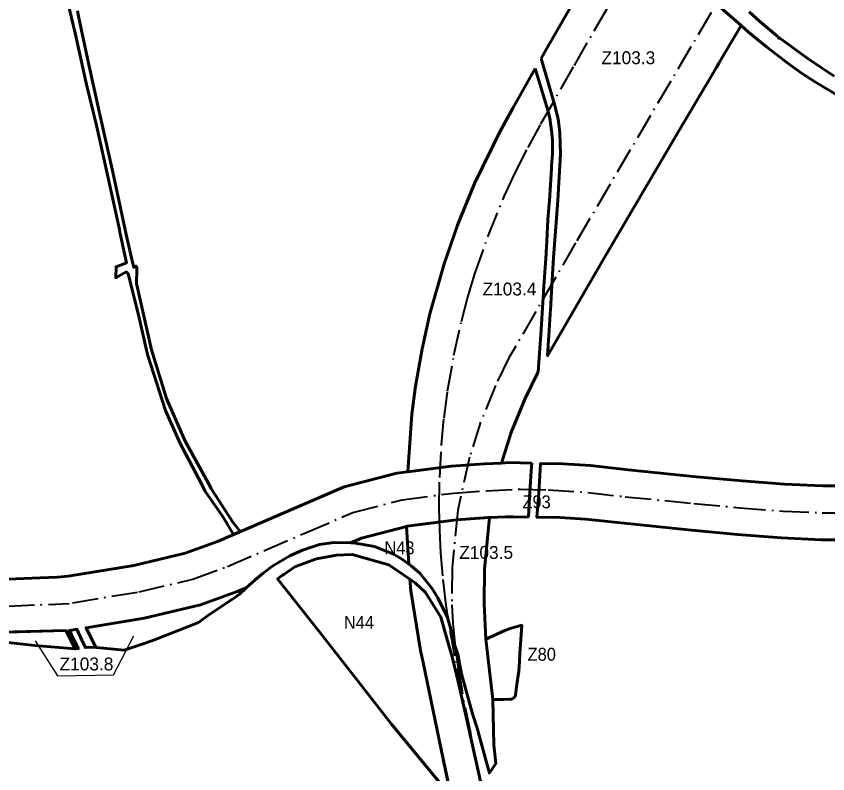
# Model space of a CAD drawing. Extents: x -650277 to -643420, y -1073980 to -1066720.
# Drawn here: x -648765 to -647259, y -1069529 to -1068122 of the extents above; entities that cross this region are included whole.
import ezdxf

# ---------------------------------------------------------------- set-up
doc = ezdxf.new("R2010")
doc.units = 0
doc.header["$LTSCALE"] = 9.6
doc.linetypes.add('DOT_DASHED', pattern=[7.7, 5, -1.2, 0.3, -1.2])
for name, color, linetype, lineweight in [('15', 7, 'Continuous', 60), ('42', 7, 'Continuous', 60), ('60', 7, 'Continuous', 60), ('61', 7, 'Continuous', 60), ('62', 7, 'DOT_DASHED', 40), ('63', 7, 'Continuous', 25), ('9', 7, 'Continuous', 60)]:
    doc.layers.add(name, color=color, linetype=linetype, lineweight=lineweight)

msp = doc.modelspace()

# ---------------------------------------------------------------- linework, layer by layer
at = {"layer": '15'}
for points in [[(-648349.419, -1069079.223), (-648362.06, -1069084.664), (-648381.44, -1069052.48), (-648415.29, -1069003.16), (-648419.78, -1068994.25), (-648427.21, -1068980.13), (-648461.22, -1068915.44), (-648488.09, -1068854.16), (-648521.92, -1068750.34), (-648537.29, -1068681.95), (-648557.4, -1068599.9), (-648559.44, -1068598.37), (-648561.49, -1068596.84), (-648580.66, -1068607.64), (-648579.97, -1068587.39), (-648560.79, -1068580.12), (-648572.95, -1068522.97), (-648573.96, -1068518.34), (-648594.38, -1068425.02), (-648615.87, -1068327.3), (-648634.84, -1068248.76), (-648655.88, -1068153.63), (-648662.71, -1068124.76), (-648677.61, -1068061.74)], [(-648651.89, -1068111.95), (-648649.74, -1068121.95), (-648644.73, -1068145.27), (-648630.99, -1068209.19), (-648610.14, -1068304.32), (-648587.39, -1068405.82), (-648559.91, -1068532.62), (-648549.84, -1068578.65), (-648547.25, -1068588.14), (-648542.93, -1068586.13), (-648541.74, -1068589.27)], [(-648541.74, -1068589.27), (-648541.25, -1068592.3), (-648541.89, -1068618.64), (-648514.35, -1068741.53), (-648486.25, -1068831.83), (-648451.76, -1068910.91), (-648409.15, -1068988.44), (-648402.76, -1069000.2), (-648363.11, -1069061.72), (-648349.419, -1069079.223)]]:
    msp.add_lwpolyline(points, dxfattribs=at)
at = {"layer": '42'}
msp.add_lwpolyline([(-648100.37, -1069107.1), (-648065.16, -1069121.12), (-648048.06, -1069130.81), (-648036.291, -1069139.458), (-648040.705, -1069069.547), (-648124.327, -1069091.181), (-648144.867, -1069099.987), (-648139.27, -1069100.05), (-648100.37, -1069107.1)], close=True, dxfattribs=at)
at = {"layer": '60'}
for points in [[(-647618.773, -1067899.914), (-647553.628, -1067999.427), (-647472.338, -1068093.096), (-647419.713, -1068138.871)], [(-647246.8, -1068233.08), (-647295.47, -1068201.09), (-647347.74, -1068162.54), (-647349.59, -1068163.24), (-647350.6, -1068160.26), (-647353.81, -1068157.67), (-647385.13, -1068131.51), (-647405.026, -1068113.904)], [(-647419.713, -1068138.871), (-647405.71, -1068151.74), (-647372.38, -1068179.01), (-647337.74, -1068205.67), (-647334.62, -1068208.02), (-647307.39, -1068227.44), (-647281.64, -1068244.34), (-647234.11, -1068273.04), (-647230.83, -1068274.93), (-647174.56, -1068306.35), (-647142.788, -1068322.462), (-647130.29, -1068328.8), (-647079.16, -1068357.01), (-647032.91, -1068382.51), (-647029.23, -1068384.46), (-646997.06, -1068401.37), (-646929.56, -1068435.42), (-646927.06, -1068436.66)], [(-647864.531, -1068951.823), (-647895.901, -1068953.392), (-647958.168, -1068957.73), (-648038.596, -1068968.281), (-648038.759, -1068968.54)], [(-647808.28, -1068952.066), (-647850.043, -1068951.098), (-647864.531, -1068951.823)], [(-647814.401, -1069052.246), (-647812.34, -1069014.54), (-647808.67, -1068958.06), (-647808.28, -1068952.066)], [(-647199.672, -1068994.255), (-647268.348, -1068994.255), (-647338.816, -1068991.19), (-647417.895, -1068984.986), (-647502.412, -1068977.157), (-647629.424, -1068964.608), (-647699.561, -1068956.635), (-647749.978, -1068953.416), (-647792.01, -1068952.442), (-647794.21, -1068986.12), (-647796.13, -1069015.57), (-647798.631, -1069052.508), (-647756.441, -1069053.207), (-647708.401, -1069056.275), (-647511.94, -1069076.703), (-647426.417, -1069084.624), (-647344.902, -1069091.02), (-647270.522, -1069094.255), (-647197.498, -1069094.255)], [(-648038.759, -1068968.54), (-648038.746, -1068968.301), (-648058.764, -1068970.927), (-648156.739, -1068996.273), (-648392.002, -1069097.554), (-648451.865, -1069119.456), (-648547.243, -1069141.81), (-648668.959, -1069161.838), (-648688.912, -1069163.603), (-648721.315, -1069164.952), (-648781.015, -1069167.44)], [(-648040.705, -1069069.547), (-648039.666, -1069069.279), (-647948.18, -1069057.276), (-647886.615, -1069053.052), (-647856.541, -1069051.548), (-647848.615, -1069051.679), (-647842.888, -1069051.774), (-647814.401, -1069052.246)], [(-648918.889, -1069268.875), (-648673.267, -1069262.895), (-648656.242, -1069297.116), (-648650.06, -1069296.39), (-648650.58, -1069295.34), (-648658.18, -1069280.27), (-648666.827, -1069262.738), (-648665.007, -1069262.694), (-648665.007, -1069262.694), (-648652.716, -1069260.657), (-648642.74, -1069281.93), (-648636.85, -1069294.49), (-648630.82, -1069293.63), (-648617.434, -1069294.508), (-648635.818, -1069257.857), (-648527.693, -1069239.938), (-648423.173, -1069215.44), (-648354.978, -1069190.492), (-648338.523, -1069183.389), (-648322.14, -1069168.56), (-648306.83, -1069156.57), (-648289.25, -1069142.79), (-648257.5, -1069124.41), (-648234.22, -1069113.6), (-648202.46, -1069103.3), (-648175.65, -1069099.64), (-648144.866, -1069099.987), (-648124.327, -1069091.181), (-648040.705, -1069069.547)], [(-648354.978, -1069190.492), (-648423.173, -1069215.44), (-648527.693, -1069239.938), (-648635.818, -1069257.857)], [(-648526.15, -1069286.21), (-648508.95, -1069280.01), (-648427.08, -1069247.75), (-648407.73, -1069233.88), (-648389.91, -1069221.86), (-648355.81, -1069198.88), (-648351.77, -1069195.88), (-648338.523, -1069183.389), (-648354.978, -1069190.492)], [(-648635.818, -1069257.857), (-648622.995, -1069283.455), (-648617.434, -1069294.508)], [(-648617.434, -1069294.508), (-648609.425, -1069295.033), (-648603.228, -1069295.53), (-648565.18, -1069299.46), (-648526.15, -1069286.21)]]:
    msp.add_lwpolyline(points, dxfattribs=at)
for points in [[(-647860.52, -1069390.72), (-647848.24, -1069390.65), (-647845.25, -1069390.07), (-647843.41, -1069389.23), (-647841.81, -1069387.99), (-647840.42, -1069386.51), (-647839.4, -1069384.73), (-647838.79, -1069382.86), (-647836.2, -1069362.68), (-647832.29, -1069338.58), (-647832.29, -1069338.58), (-647831.19, -1069320.69), (-647830.23, -1069305.38), (-647826.928, -1069253.199), (-647848.17, -1069259.21), (-647858.37, -1069263.03), (-647893.553, -1069279.017), (-647880.326, -1069390.832)], [(-648730.66, -1069290.43), (-648656.242, -1069297.116), (-648673.267, -1069262.895), (-648761.189, -1069265.035), (-648918.889, -1069268.875), (-648909.86, -1069270.02), (-648861.49, -1069275.34), (-648785.92, -1069284.2), (-648730.66, -1069290.43)]]:
    msp.add_lwpolyline(points, close=True, dxfattribs=at)
msp.add_arc((-648354.978, -1069190.492), 0.000000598, 264.13978, 298.69712, dxfattribs=at)
at = {"layer": '61'}
msp.add_line((-648038.596, -1068968.281), (-647958.168, -1068957.73), dxfattribs=at)
for points in [[(-647464.94, -1068215.752), (-647461.188, -1068209.373), (-647419.713, -1068138.871), (-647472.338, -1068093.096), (-647553.628, -1067999.427), (-647618.773, -1067899.914), (-647685.819, -1068016.861)], [(-647685.819, -1068016.861), (-647781.346, -1068183.485), (-647791.055, -1068200.507)], [(-647791.055, -1068200.507), (-647765.22, -1068287.94), (-647759.412, -1068313.436)], [(-647768.02, -1068570.36), (-647770.94, -1068622.47), (-647772.85, -1068656.41), (-647773.08, -1068660.57), (-647773.4, -1068665.71), (-647776.5, -1068714.8), (-647778.95, -1068752.433), (-647675.054, -1068572.919), (-647535.844, -1068336.279), (-647464.94, -1068215.752)], [(-647801.797, -1068219.34), (-647843.6, -1068292.629), (-647868.214, -1068337.803), (-647914.339, -1068432.512), (-647946.187, -1068510.254), (-647971.074, -1068581.98), (-647997.27, -1068674.747), (-648011.775, -1068739.718), (-648023.914, -1068809.332), (-648030.73, -1068861.213), (-648038.596, -1068968.281)], [(-647771.413, -1068334.626), (-647774.94, -1068311.47), (-647779.55, -1068292.23), (-647780.07, -1068290.53), (-647801.797, -1068219.34)], [(-647759.412, -1068313.436), (-647758.45, -1068317.66), (-647756.09, -1068337.61), (-647754.99, -1068378.21), (-647757.41, -1068419.98), (-647760.22, -1068463.96), (-647768.02, -1068570.36)], [(-647796.173, -1068782.191), (-647791.77, -1068713.23), (-647786.47, -1068634.37), (-647786.32, -1068632.19), (-647781.85, -1068562.97), (-647781.55, -1068558.38), (-647781.13, -1068551.88), (-647778.24, -1068499.95), (-647775.82, -1068469.74), (-647775.52, -1068464.97), (-647771.74, -1068404.5), (-647771.47, -1068400.07), (-647770.12, -1068377.5), (-647769.92, -1068352.1), (-647770.81, -1068340.29), (-647771.05, -1068337.01), (-647771.413, -1068334.626)], [(-647846.989, -1068896.545), (-647820.883, -1068832.117), (-647797.632, -1068784.713), (-647796.173, -1068782.191)], [(-647958.168, -1068957.73), (-647895.901, -1068953.392), (-647864.531, -1068951.823), (-647847.197, -1068897.199), (-647847.034, -1068896.687), (-647846.989, -1068896.545)], [(-647948.18, -1069057.276), (-648039.666, -1069069.279), (-648040.705, -1069069.548), (-648036.291, -1069139.458)], [(-647886.615, -1069053.052), (-647889.927, -1069053.218), (-647948.18, -1069057.276)], [(-647893.553, -1069279.017), (-647896.67, -1069213.573), (-647896.362, -1069149.171), (-647886.615, -1069053.052)], [(-648036.291, -1069139.458), (-648031.92, -1069142.67), (-648016.36, -1069156.54), (-647993.8, -1069184.11)], [(-648005.47, -1069192.09), (-648024.02, -1069174.7), (-648034.421, -1069167.61)], [(-648034.421, -1069167.61), (-648034.421, -1069167.61), (-648033, -1069189), (-648015, -1069300), (-648010.092, -1069322.087), (-647980.331, -1069465.915), (-647958.34, -1069570.699), (-647925.99, -1069608.57), (-647906.16, -1069641.48), (-647885.665, -1069678.788), (-647885.663, -1069678.794), (-647883.51, -1069682.71), (-647875.82, -1069701.85), (-647875.82, -1069701.85), (-647864.19, -1069735.12), (-647858.44, -1069749.43), (-647852.63, -1069775.7), (-647850.66, -1069785.74), (-647849.165, -1069793.367)], [(-647962.2, -1069290.88), (-647974.81, -1069246.86), (-647977.29, -1069238.21), (-648005.47, -1069192.09)], [(-647993.8, -1069184.11), (-647982.58, -1069202.33), (-647965.06, -1069238.95), (-647957.56, -1069264.74), (-647953.01, -1069285.73), (-647951.841, -1069289.09)], [(-647880.326, -1069390.832), (-647880.326, -1069390.832), (-647893.553, -1069279.017)], [(-647852.78, -1069745.71), (-647859.722, -1069722.428), (-647872.87, -1069673.56), (-647892.79, -1069591.06), (-647892.789, -1069591.06), (-647893.75, -1069587.08), (-647922.04, -1069459.71), (-647925.16, -1069445.68), (-647928.41, -1069431.03), (-647945.28, -1069355.1), (-647956.27, -1069311.58), (-647962.2, -1069290.88)], [(-647951.841, -1069289.09), (-647945.63, -1069306.95), (-647938.77, -1069343.17), (-647918.08, -1069417.43), (-647909.67, -1069444.46), (-647889.22, -1069519.32), (-647887.087, -1069527.229), (-647885.782, -1069525.389), (-647882.551, -1069520.835), (-647878.73, -1069515.45)], [(-647878.73, -1069515.45), (-647874.75, -1069509.84), (-647878.93, -1069475.09), (-647880.318, -1069391.297), (-647880.326, -1069390.832)]]:
    msp.add_lwpolyline(points, dxfattribs=at)
at = {"layer": '62'}
for points in [[(-647128.118, -1067439.088), (-647164.761, -1067539.408), (-647210.113, -1067645.071), (-647251.182, -1067728.502), (-647325.296, -1067860.04), (-647512.903, -1068178.95), (-647726.877, -1068542.68), (-647850.594, -1068756.441), (-647875.691, -1068807.609), (-647903.473, -1068876.174), (-647924.037, -1068940.973), (-647945.559, -1069039.601), (-647956.348, -1069145.994), (-647956.677, -1069214.977), (-647954.925, -1069248.93), (-647950.785, -1069292.731), (-647945.699, -1069329.377), (-647937.748, -1069374.683)], [(-647904.75, -1069533.925), (-647921.593, -1069453.674), (-647951.177, -1069310.704), (-647961.781, -1069251.651), (-647967.108, -1069216.048), (-647973.483, -1069161.422), (-647976.974, -1069118.566), (-647979.115, -1069076.622), (-647979.994, -1069035.633), (-647979.227, -1068978.642), (-647975.845, -1068917.741), (-647971.102, -1068867.969), (-647964.589, -1068818.397), (-647952.909, -1068751.415), (-647938.965, -1068688.958), (-647927.463, -1068645.455), (-647913.969, -1068600.436), (-647890.042, -1068531.477), (-647859.34, -1068456.533), (-647839.124, -1068413.001), (-647815.115, -1068365.753), (-647791.193, -1068321.849), (-647729.261, -1068213.27), (-647633.767, -1068046.703)], [(-647953.174, -1069007.503), (-647892.914, -1069003.305), (-647829.936, -1069000.155), (-647777.98, -1069001.73), (-647703.981, -1069006.455), (-647634.706, -1069014.33), (-647507.176, -1069026.93), (-647422.156, -1069034.805), (-647341.859, -1069041.105), (-647269.435, -1069044.255), (-647198.585, -1069044.255), (-647126.161, -1069041.105), (-647071.055, -1069037.955), (-646992.775, -1069025.505), (-646951.398, -1069008.03), (-646907.314, -1068982.831), (-646861.655, -1068949.756), (-646819.145, -1068907.232), (-646779.784, -1068863.132), (-646712.083, -1068781.233), (-646669.79, -1068726.705)], [(-648660.841, -1069211.175), (-648537.468, -1069190.874), (-648437.519, -1069167.448), (-648373.49, -1069144.023), (-648228.701, -1069081.527), (-648140.533, -1069043.727), (-648049.215, -1069020.103), (-647953.174, -1069007.503)], [(-649319.032, -1069251.01), (-649228.433, -1069229.954), (-649166.697, -1069221.478), (-649075.909, -1069222.689), (-648779.53, -1069217.422), (-648667.088, -1069212.737)]]:
    msp.add_lwpolyline(points, dxfattribs=at)
at = {"layer": '63'}
msp.add_lwpolyline([(-648730, -1069282), (-648689.019, -1069347.095), (-648585, -1069345.095), (-648547, -1069273)], dxfattribs=at)
at = {"layer": '9'}
msp.add_lwpolyline([(-648015, -1069300), (-648033, -1069189), (-648034.421, -1069167.61), (-648071.9, -1069142.06), (-648073.66, -1069140.86), (-648141.92, -1069121.66), (-648171.14, -1069122.83), (-648207.77, -1069129.95), (-648209.89, -1069130.36), (-648226.51, -1069136.57), (-648248.14, -1069144.65), (-648268.87, -1069158.61), (-648270.92, -1069159.99), (-648275.19, -1069162.87), (-648280.1, -1069166.97), (-648203.01, -1069264.73), (-648127.77, -1069361.38), (-648068.71, -1069436.57), (-647967.53, -1069559.94), (-647958.214, -1069571.3), (-647980.331, -1069465.915), (-648010.092, -1069322.087)], close=True, dxfattribs=at)

# ---------------------------------------------------------------- texts
at = {"layer": '63'}
for s, p in [('Z103.3', (-647679, -1068211)), ('Z103.4', (-647899.646, -1068640.598)), ('Z103.5', (-647942.96, -1069129.881)), ('Z103.8', (-648685, -1069337))]:
    msp.add_text(s, height=24, dxfattribs=at).set_placement(p)
at = {"layer": '63', "width": 0.95}
for s, p in [('Z93', (-647825.651, -1069035.867)), ('N43', (-648081.963, -1069121.387)), ('N44', (-648157.12, -1069259.712)), ('Z80', (-647816, -1069319))]:
    msp.add_text(s, height=24, dxfattribs=at).set_placement(p)

doc.saveas('drawing.dxf')
